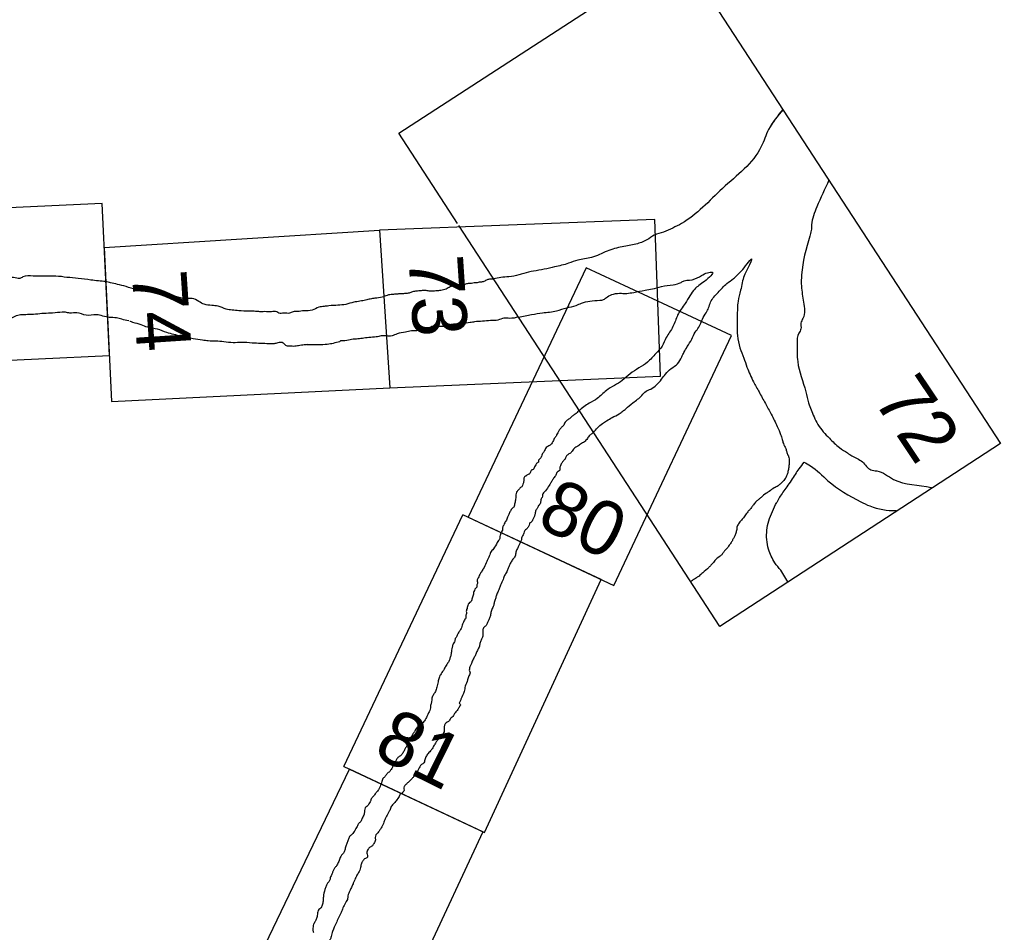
# Model space of a CAD drawing. Extents: x 3953924 to 3974542, y 193747 to 216192.
# Drawn here: x 3962352 to 3963404, y 199042 to 200020 of the extents above; entities that cross this region are included whole.
import ezdxf

# ---------------------------------------------------------------- set-up
doc = ezdxf.new("R2010")
doc.units = 0
doc.layers.add('V-ANNO-NPLT', color=7, linetype='Continuous')

msp = doc.modelspace()

# ---------------------------------------------------------------- linework, layer by layer
at = {"layer": 'V-ANNO-NPLT'}
for p, q in [((3962737.9, 199794.5), (3962749, 199625.4)), ((3963175.8, 199417.6), (3963168.1, 199429.9))]:
    msp.add_line(p, q, dxfattribs=at)
for points in [[(3962758.7, 199898.3), (3963059.7, 200094), (3963403.6, 199565.8), (3963102.7, 199369.7)], [(3962821.6, 199801.6), (3962758.7, 199898.3)], [(3962440.7, 199823.2), (3962163.5, 199810.2)], [(3962448.5, 199660.1), (3962440.7, 199823.2)], [(3962163.5, 199810.2), (3962143.7, 199645.8), (3962448.5, 199660.1)], [(3962737.9, 199794.5), (3962749, 199625.4), (3963039.3, 199637.8), (3963033.3, 199806)], [(3963033.3, 199806), (3962737.9, 199794.5)], [(3962442.9, 199775.9), (3962737.9, 199794.5)], [(3963023.1, 199492.1), (3962822.9, 199799.5)], [(3962442.9, 199775.9), (3962450.8, 199610.7), (3962749, 199625.4)], [(3962959.4, 199754), (3962915.2, 199660.4)], [(3963036.3, 199718.2), (3962959.4, 199754)], [(3962833.1, 199486.7), (3962989.2, 199413.6), (3963115.2, 199681.4), (3963036.3, 199718.2)], [(3962915.2, 199660.4), (3962833.1, 199486.7)], [(3962699.8, 199219.7), (3962827.4, 199489.4)], [(3962975.7, 199420), (3962827.4, 199489.4)], [(3963102.7, 199369.7), (3963023.1, 199492.1)], [(3962699.8, 199219.7), (3962850.6, 199148.7), (3962975.7, 199420)], [(3962722.4, 198877.9), (3962576.5, 198947.1), (3962705.8, 199216.8)], [(3962848.6, 199149.6), (3962705.8, 199216.8)], [(3962848.6, 199149.6), (3962722.4, 198877.9)]]:
    msp.add_lwpolyline(points, dxfattribs=at)
for points in [[(3963170.6, 199923.9), (3963155.1, 199902.3), (3963147.2, 199884), (3963105.7, 199839.2), (3963061.9, 199801.6), (3963042.3, 199792.4)], [(3963170.5, 199923.8), (3963155.1, 199902.3), (3963147.2, 199884), (3963105.7, 199839.2), (3963061.9, 199801.6), (3963042.3, 199792.4)], [(3963219.8, 199848), (3963206.8, 199819.4), (3963201.2, 199800.1), (3963200.8, 199794), (3963199.3, 199788.1), (3963190.5, 199746.7), (3963190.3, 199734.3), (3963192.6, 199717.3), (3963191.9, 199699.8), (3963189.7, 199694.9), (3963189.8, 199688.7), (3963187.4, 199684.1), (3963185.7, 199673.2), (3963186.3, 199653.6), (3963194.9, 199621.3), (3963198, 199609.2), (3963203.8, 199594.5), (3963208, 199586.1), (3963220.3, 199571.4), (3963231, 199561.4), (3963239.8, 199555.6), (3963244.3, 199552.7), (3963255.7, 199546.1), (3963264.8, 199537.5), (3963271.1, 199536.4), (3963289.1, 199527.3), (3963329.4, 199518.5), (3963330.6, 199518.2)], [(3963042.3, 199792.4), (3963032.5, 199789), (3963024.6, 199784.1), (3963012.9, 199779.5), (3962998.2, 199776.7), (3962982, 199772), (3962965.2, 199765.1), (3962950.5, 199762.3), (3962940.7, 199759), (3962925.7, 199755), (3962914.6, 199752.6), (3962903, 199750.5), (3962892.7, 199748.1), (3962887.3, 199746.5), (3962876.7, 199744.5), (3962868.1, 199743.7), (3962860.3, 199742.2)], [(3962967.3, 199577.5), (3962976.9, 199587.2), (3962981.5, 199590.1), (3962987.4, 199593.7), (3962995, 199597.6), (3962998.8, 199600.4), (3963002, 199603), (3963009.6, 199609.4), (3963019.3, 199617.3), (3963023.7, 199621.9), (3963028.7, 199624.1), (3963040.3, 199634.7), (3963044.5, 199640.1), (3963050.6, 199646.1), (3963057.5, 199651.2), (3963062, 199658.6), (3963064.4, 199663.5), (3963067.9, 199669.6), (3963072.7, 199677.7), (3963076.5, 199685), (3963080.2, 199690.5), (3963084.2, 199699.1), (3963088.1, 199706), (3963090.8, 199711.3), (3963092.9, 199717.2), (3963101, 199727.7), (3963110.5, 199737.4), (3963117.3, 199742.5), (3963125.9, 199750.7), (3963132.3, 199758.5), (3963136.8, 199763.6), (3963133.3, 199754.3), (3963128.8, 199745.4), (3963125.1, 199730.1), (3963122.4, 199718.3), (3963121.5, 199702.2), (3963121.7, 199681.4), (3963124.4, 199668.4), (3963128.5, 199657.4), (3963131.9, 199647.6), (3963139, 199631.9), (3963144.9, 199621), (3963151.6, 199608.8), (3963157.9, 199597.2), (3963164.4, 199584), (3963168, 199575.3), (3963169.7, 199570.2)], [(3962886.9, 199701.3), (3962901.1, 199704), (3962912.7, 199705.9), (3962927.8, 199708), (3962938.8, 199711.3), (3962948.9, 199713.8), (3962954.5, 199716.2), (3962963.5, 199718.3), (3962974.1, 199719.4), (3962978.2, 199720.1), (3962982.4, 199723), (3962988.8, 199726), (3962997.4, 199726.8), (3963003, 199726.7), (3963010.5, 199727.8), (3963022.8, 199730), (3963030.5, 199731.5), (3963040.2, 199734), (3963052.9, 199736), (3963061.3, 199738.5), (3963062.2, 199739.1), (3963073.2, 199741.4), (3963083.3, 199745.9), (3963089.6, 199748.9), (3963094.7, 199749.4), (3963086.3, 199739.6), (3963075.9, 199731.3), (3963065.8, 199716), (3963057.6, 199703.4), (3963052.6, 199691.1), (3963045.4, 199679.3), (3963041, 199670.2), (3963034.1, 199662.2), (3963025.3, 199653.1), (3963006.6, 199640.5), (3962998.3, 199633.4), (3962989.9, 199628), (3962981.2, 199622.7), (3962971.5, 199614.1), (3962962.8, 199608.9), (3962951.6, 199601)], [(3962444.5, 199739.3), (3962428.7, 199741), (3962415, 199742.8), (3962402.9, 199743.9), (3962391.1, 199745.2), (3962377, 199745.1), (3962366.6, 199745.2), (3962355.7, 199744.3), (3962352.3, 199742.8), (3962345.8, 199743.6), (3962341.8, 199743.8), (3962332.4, 199742.3), (3962321.3, 199739.2), (3962301.5, 199736)], [(3962597.9, 199707.5), (3962587.2, 199708.1), (3962580, 199708.8), (3962573.6, 199709.9), (3962565, 199712.9), (3962558.2, 199713.8), (3962550.2, 199715), (3962544.2, 199718), (3962537, 199721.2), (3962529.9, 199720.9), (3962519.6, 199723.3), (3962510.4, 199724.8), (3962502.7, 199727.2), (3962498.4, 199726.6), (3962492.5, 199728.6), (3962477.1, 199730.8), (3962466.3, 199734), (3962457, 199736.4), (3962449.7, 199738.1), (3962444.5, 199739.3)], [(3962860.3, 199742.2), (3962857.6, 199742), (3962854.1, 199741.5), (3962851.7, 199740.4), (3962849.9, 199739.3), (3962846.3, 199738.8), (3962843.6, 199738.3), (3962839.5, 199737.9), (3962836.5, 199737.3), (3962831.9, 199737.1), (3962828.8, 199735.9), (3962822.9, 199735.7), (3962819.6, 199734.9), (3962814.9, 199734.1), (3962810.7, 199731.9), (3962805, 199730.1), (3962799.8, 199729.4), (3962794.4, 199729), (3962790, 199729.3), (3962786.2, 199729.9), (3962781.3, 199729.4), (3962776.5, 199729), (3962772.3, 199728.1), (3962768.8, 199726.8), (3962764.8, 199726.4), (3962760.5, 199726.3), (3962756.5, 199725.9), (3962751.9, 199725.6), (3962746.2, 199724.6), (3962740.9, 199722.6), (3962733, 199721.5), (3962728.1, 199720.6), (3962723.1, 199719.5)], [(3962723.1, 199719.5), (3962717, 199718.3), (3962710.4, 199717.2), (3962702, 199714.9), (3962693.5, 199714), (3962683.6, 199713.3), (3962678.5, 199712.7), (3962673, 199711.8), (3962665.9, 199708.7), (3962657.3, 199708), (3962650, 199707.3), (3962645.5, 199707.1), (3962641.4, 199705.4), (3962635.6, 199705.6), (3962630.1, 199705.6), (3962628, 199706.9), (3962622.3, 199707.1), (3962616.7, 199707.1), (3962609.8, 199707.1), (3962604.9, 199707.4), (3962600.5, 199707.7), (3962597.9, 199707.5)], [(3962469.2, 199697.1), (3962461.6, 199698.9), (3962456.2, 199700.4), (3962448.3, 199700.9), (3962434.5, 199703.7), (3962423.4, 199703.3), (3962413.6, 199705.9), (3962406.1, 199705.6), (3962401.3, 199706.4), (3962397.9, 199706.5), (3962387.6, 199705.5), (3962378.5, 199705.2), (3962369.3, 199704.3), (3962360.8, 199703.9), (3962353.3, 199703.6), (3962346.9, 199701.8), (3962341.8, 199700.2), (3962339.2, 199701.9), (3962337.1, 199701.7), (3962334, 199699.7), (3962315.3, 199700.5)], [(3962886.9, 199701.3), (3962877.5, 199699.9), (3962871.4, 199700), (3962864.9, 199698.1), (3962857.1, 199697.5), (3962848.5, 199696.8), (3962839.9, 199696.2), (3962835.2, 199695.4), (3962826.3, 199694.5), (3962819, 199693.8), (3962812.8, 199692.9), (3962807.7, 199691.4), (3962802.6, 199691.3), (3962797.9, 199691.3), (3962794.1, 199691.1), (3962790.3, 199688.3), (3962785.8, 199688), (3962781.6, 199687.1), (3962777.5, 199686.7), (3962772.2, 199686.4), (3962765.8, 199685), (3962756.9, 199683.3), (3962751.4, 199681.1), (3962745.3, 199681.2)], [(3962619.6, 199672.7), (3962601.5, 199673.5), (3962590.2, 199674.2), (3962581.2, 199673.8), (3962571.2, 199674.8), (3962562.5, 199675.5), (3962554.5, 199675.7), (3962548.3, 199676.5), (3962538.1, 199677.9), (3962525.4, 199680.8), (3962510.1, 199684.7), (3962500.1, 199688.3), (3962489.4, 199690.4), (3962482.6, 199692.9), (3962473.7, 199695.6), (3962470.4, 199696.7)], [(3962745.3, 199681.2), (3962739.8, 199681.2), (3962734.5, 199680), (3962726.7, 199679.4), (3962719.6, 199678.4), (3962713.2, 199677.8), (3962706.4, 199677), (3962699, 199675.8), (3962695.4, 199675.3), (3962695.3, 199675.2)], [(3962660.4, 199671.8), (3962658.7, 199671.6), (3962652.7, 199670.8), (3962647.2, 199670), (3962641.2, 199670.1), (3962637.6, 199670.9), (3962634.8, 199673.4), (3962629, 199673.6), (3962624.9, 199672.7), (3962619.6, 199672.7)], [(3962660.4, 199671.8), (3962672.4, 199671.9), (3962682, 199672.3), (3962695.3, 199675.2)], [(3962951.6, 199601), (3962947.8, 199597.1), (3962945.3, 199595.6), (3962943.7, 199594.3), (3962942.3, 199592.9), (3962940.7, 199591.9), (3962939.2, 199590.7), (3962937.7, 199589.4), (3962936.4, 199587.5), (3962935.6, 199585.6), (3962933.7, 199583.8), (3962931.8, 199581.5), (3962930.5, 199579.9), (3962929.1, 199577.3), (3962927.9, 199575.2), (3962927.2, 199573.6), (3962925.4, 199571.1), (3962924.4, 199569.1), (3962921.6, 199564.6), (3962918.6, 199562.7), (3962916.7, 199561.5)], [(3962967.3, 199577.5), (3962964.9, 199575.8), (3962962, 199573.1), (3962960.9, 199571.1), (3962959.2, 199569.2), (3962957.8, 199567.5), (3962955.6, 199566.4), (3962953.5, 199565), (3962951.5, 199563.5), (3962948.4, 199561.8), (3962946.6, 199560.4), (3962945.3, 199558.7), (3962943.9, 199556.7), (3962941.1, 199554.6), (3962938.6, 199552.5), (3962937.1, 199549.5), (3962934.9, 199546.9), (3962932.9, 199543.9), (3962931.9, 199541.8), (3962931.3, 199539), (3962931.2, 199537.2), (3962929.4, 199535.8), (3962928.1, 199534.7), (3962927.5, 199532.8), (3962926.7, 199531.2), (3962925.4, 199529.5), (3962924, 199527.4), (3962922.4, 199524.9), (3962921.4, 199523.1), (3962919.8, 199520.9), (3962915.9, 199514.9), (3962912.7, 199510.6), (3962912.3, 199507.9), (3962911.2, 199506.4), (3962910.8, 199504.1)], [(3962916.7, 199561.5), (3962915.5, 199559.4), (3962914.2, 199556.9), (3962912.5, 199554.3), (3962911.6, 199552)], [(3963169.7, 199570.2), (3963170.9, 199565.8), (3963173.6, 199560.3), (3963174.1, 199558.6), (3963175.1, 199555.1), (3963176.6, 199551.7), (3963177.1, 199547.2), (3963177, 199543.3), (3963176.6, 199538.9), (3963175.6, 199534.5), (3963174.4, 199531), (3963172.2, 199527.3), (3963168.2, 199523), (3963165.4, 199520.5), (3963161.2, 199518.1), (3963155.6, 199514.5), (3963152.7, 199512.5), (3963147, 199508), (3963144.5, 199505.8)], [(3962911.6, 199552), (3962911.3, 199551.1), (3962910.6, 199550.1), (3962909.7, 199549.3), (3962908.6, 199547.8), (3962908.6, 199547.4), (3962908.3, 199546.1), (3962908.3, 199545.6), (3962907.2, 199545.2), (3962905.6, 199542.8), (3962904.3, 199540.9), (3962901.9, 199537.4), (3962900.9, 199537.3), (3962900.1, 199536.3), (3962899.4, 199534.4), (3962898.7, 199533.2), (3962898.1, 199532.8), (3962896.8, 199532.3)], [(3963192.9, 199545.9), (3963187.6, 199538.7), (3963183.5, 199532.7), (3963179.2, 199526.1), (3963174.6, 199519.3), (3963170.5, 199513.5), (3963166.7, 199508.1), (3963163.9, 199502.7)], [(3963192.9, 199545.9), (3963200.1, 199541.8), (3963218.7, 199525.9), (3963253.8, 199503.4), (3963263.8, 199498.8), (3963291.6, 199493.8), (3963291.8, 199493.8)], [(3962896.8, 199532.3), (3962895.3, 199531.2), (3962894.3, 199530.6), (3962892.9, 199529.4), (3962892.6, 199528.1), (3962892.6, 199526.2), (3962892.5, 199524.6), (3962892.3, 199523.5), (3962891.2, 199520.8), (3962890.4, 199519.4), (3962889.3, 199518.5), (3962887.9, 199517.1), (3962886.9, 199516.1), (3962885.9, 199515), (3962885, 199513.8), (3962884.5, 199512.3)], [(3962884.5, 199512.3), (3962884.1, 199509.1), (3962883.9, 199506.2), (3962883.1, 199501.9), (3962882.6, 199499.4), (3962882.4, 199498.3)], [(3962882.4, 199498.3), (3962882.3, 199498.1), (3962881.3, 199497.1), (3962880.4, 199496.3), (3962878.3, 199493.3), (3962876.6, 199489.7), (3962875.3, 199486.9), (3962874.6, 199484.5), (3962873.5, 199482.7), (3962871.1, 199478.4), (3962869.9, 199475.4), (3962869.9, 199472.7), (3962868.6, 199470.7), (3962867.8, 199468.5), (3962867.3, 199467.4), (3962867.1, 199464.7), (3962865.7, 199461.9), (3962864.2, 199459.6), (3962860.2, 199452.9), (3962857.1, 199449), (3962855.2, 199443.9), (3962853.7, 199441), (3962852.4, 199437.7), (3962849.2, 199431.5), (3962847.2, 199428), (3962845.6, 199425.3), (3962843.2, 199420.5), (3962842.7, 199419), (3962843.1, 199417.1), (3962842.3, 199414.3)], [(3962910.8, 199504.1), (3962909.6, 199500.4), (3962908.6, 199499.2), (3962907.8, 199497.5), (3962906.2, 199495), (3962905.4, 199493.3), (3962904.5, 199489.5), (3962902.1, 199483.6), (3962901.1, 199481.8), (3962899.2, 199480.6), (3962898.3, 199478.2), (3962896.8, 199475.5), (3962895.5, 199473.8), (3962893.7, 199472.4), (3962892.8, 199469.5), (3962891.9, 199467.7), (3962890.8, 199466.1), (3962890.1, 199462.5), (3962888.9, 199459.7), (3962888.1, 199457.7), (3962886.6, 199454.9), (3962885.8, 199453.3), (3962884.2, 199449.3), (3962883.3, 199444.9), (3962880.9, 199441.7), (3962878.7, 199438.2), (3962876.5, 199433.6), (3962875.3, 199430.4), (3962873.2, 199426.2), (3962871.1, 199422.5), (3962870.5, 199420.1)], [(3963144.5, 199505.8), (3963141.9, 199503.6), (3963138.8, 199500.1), (3963136.7, 199497.2), (3963135.1, 199495), (3963132.8, 199492.6), (3963129.7, 199488.1), (3963126.8, 199484.5), (3963123.5, 199480.7), (3963121.5, 199477), (3963120.7, 199472.6), (3963119.6, 199468.6), (3963118.2, 199465.2), (3963116.5, 199462.5), (3963116, 199461.2)], [(3963168.1, 199429.9), (3963161.8, 199437.9), (3963155.1, 199452.4), (3963153.1, 199462.8), (3963155.3, 199482.8), (3963163.9, 199502.7)], [(3963116, 199461.2), (3963113.8, 199457.9), (3963110.3, 199453.3), (3963108, 199450.7), (3963106.2, 199448.4), (3963104.3, 199445.9), (3963099.5, 199442.5), (3963095.9, 199438.2), (3963093.2, 199435.3), (3963091, 199432.8), (3963084.5, 199427.2), (3963080.5, 199423.7), (3963077.7, 199421.9)], [(3962870.5, 199420.1), (3962867.6, 199413.8), (3962866.2, 199410), (3962865.3, 199407.6), (3962863.3, 199403.2), (3962862.4, 199399.4), (3962861, 199395.5), (3962860.7, 199393.6), (3962858.9, 199388.9), (3962857.5, 199384.5), (3962856.6, 199380.4), (3962855.2, 199376.9), (3962853.6, 199373.8), (3962852.3, 199370.6), (3962851, 199369.5), (3962848.8, 199366.3), (3962848.8, 199363.4), (3962848.6, 199359.1), (3962847.3, 199355.9), (3962845.9, 199352.4), (3962845.1, 199348.6), (3962842.9, 199344), (3962841.1, 199339.9), (3962839.6, 199336.6), (3962837.4, 199332.6), (3962836.2, 199329.2), (3962834.7, 199326.5), (3962834.3, 199323.8)], [(3962842.3, 199414.3), (3962842.2, 199411.8), (3962841.2, 199410.6), (3962839.7, 199408.2), (3962838.9, 199406.1)], [(3963077.7, 199421.9), (3963075.5, 199420.4), (3963074, 199419.5), (3963071.5, 199417.7)], [(3962838.9, 199406.1), (3962838.6, 199404.4), (3962838, 199402.3), (3962837.4, 199400), (3962836.9, 199397.7)], [(3962836.9, 199397.7), (3962836.6, 199397.1), (3962835.4, 199395.8), (3962834.6, 199395.2), (3962833, 199393.4), (3962832.3, 199390.9), (3962831.8, 199388.8), (3962831.1, 199386.6), (3962831.1, 199384.8), (3962830.9, 199382.6), (3962830.4, 199380.6), (3962830.4, 199378.7), (3962829.5, 199377.3), (3962828.5, 199375.2), (3962827.7, 199373.5), (3962826.7, 199370.9), (3962826, 199368.3), (3962825, 199366.5), (3962824.1, 199365.1), (3962821.9, 199361.6), (3962820.8, 199359.1), (3962819.1, 199356.6)], [(3962819.1, 199356.6), (3962818.3, 199353.2), (3962817, 199350.9), (3962816, 199347.3), (3962815.3, 199344.2), (3962815, 199342.6)], [(3962815, 199342.6), (3962814.7, 199340), (3962813.8, 199336.4), (3962812.7, 199333.1), (3962811.8, 199331.2), (3962810.9, 199330.3)], [(3962810.9, 199330.4), (3962810.6, 199329.7), (3962808.3, 199325.9), (3962807.2, 199323.7), (3962804, 199319), (3962801.9, 199314.7), (3962800.8, 199310.2), (3962799.5, 199304.7), (3962797.9, 199299.8), (3962795.9, 199296.7), (3962794.2, 199292.7), (3962793.7, 199288.3), (3962792.8, 199285), (3962792, 199279.7), (3962790.2, 199276.3), (3962789.5, 199274.6), (3962788.7, 199273)], [(3962834.3, 199323.8), (3962834.4, 199321.9), (3962835, 199321), (3962833.8, 199316.7), (3962832.4, 199312.3), (3962830, 199305.7), (3962828.6, 199299.8), (3962825.3, 199291.8), (3962824.1, 199289), (3962823.5, 199287.5), (3962824.1, 199286.6), (3962824.6, 199286.3), (3962823.8, 199283.7), (3962821.9, 199280.5), (3962819, 199277.2), (3962817.3, 199274.1), (3962814.2, 199271), (3962811.8, 199267.7), (3962809.6, 199266.5), (3962807.8, 199263.7), (3962807.3, 199260.7), (3962807.4, 199258.1), (3962806.7, 199255.5), (3962804.2, 199251.9), (3962801.4, 199248.7), (3962798.7, 199245.8), (3962797.3, 199243.4), (3962796.5, 199242.3)], [(3962788.7, 199273), (3962786.8, 199269.4), (3962784.2, 199266), (3962782.3, 199263.9), (3962778.4, 199261.5), (3962775.8, 199257.5), (3962773.9, 199254.5), (3962772.7, 199252.5), (3962770.6, 199249.2), (3962768.4, 199243.6), (3962766.9, 199240.9), (3962765.1, 199238), (3962763.5, 199234.9), (3962761.1, 199231.6), (3962758.4, 199229.7), (3962756.3, 199226.9), (3962754.8, 199224.1), (3962753, 199221.2), (3962751.9, 199218.7), (3962750.4, 199216.3), (3962748.3, 199213.5), (3962746.6, 199212.5), (3962746.3, 199212)], [(3962796.5, 199242.3), (3962794.5, 199238.6), (3962791.8, 199235.4), (3962788.9, 199231.8), (3962786.9, 199227.9), (3962785.5, 199223.4), (3962783.1, 199221.6), (3962779.9, 199216.7), (3962777.9, 199213.3), (3962775.1, 199209.2), (3962772.9, 199206.6), (3962768.6, 199202.5), (3962766.2, 199200.1), (3962764.3, 199198), (3962764.1, 199195.5), (3962764.1, 199193.1), (3962762.8, 199191.7), (3962762.4, 199191.1)], [(3962746.3, 199212), (3962744.2, 199209.2), (3962741.7, 199206.5), (3962740.2, 199202.2), (3962738, 199196.7), (3962736.5, 199194), (3962733.9, 199190.9), (3962731.5, 199187.6), (3962729.2, 199184.7), (3962727.9, 199181.5), (3962726.7, 199179.6), (3962724.4, 199176.6), (3962722.6, 199175.2), (3962722, 199172.4), (3962721.5, 199168.5), (3962719.5, 199164), (3962718, 199160.7), (3962715.8, 199158.5), (3962714, 199155.2), (3962712.5, 199152.9)], [(3962762.4, 199191.1), (3962759.7, 199189.2), (3962758.9, 199187.5), (3962755.9, 199182.9), (3962752.8, 199179.2), (3962750.1, 199175.5), (3962748.5, 199171.5), (3962746.9, 199168.7), (3962744.2, 199163.5), (3962742.2, 199158.6), (3962740.9, 199155.5), (3962738.9, 199152.4), (3962737, 199149.4), (3962733.6, 199144.9), (3962733.5, 199142.2), (3962733.7, 199140.8), (3962731.9, 199137.1), (3962730.4, 199134.6), (3962727.9, 199133), (3962725.7, 199130.8), (3962724.4, 199126.7), (3962725.1, 199124.2), (3962725.3, 199122.8), (3962722.9, 199121), (3962721.3, 199119.7), (3962720.1, 199118.4), (3962719.3, 199117.3)], [(3962712.5, 199152.9), (3962711.9, 199151.5), (3962710.9, 199150), (3962709.5, 199147.8), (3962708.8, 199147.1), (3962707.5, 199146.1)], [(3962707.5, 199146.1), (3962706.5, 199145.1), (3962705.6, 199143.6), (3962704.2, 199139.8), (3962702.6, 199136.1), (3962701.3, 199132), (3962700.2, 199128.1), (3962696.5, 199123.1), (3962694.6, 199118.6), (3962693, 199114.9), (3962691.5, 199112.5), (3962690.3, 199111.2)], [(3962690.3, 199111.2), (3962688.8, 199108.4), (3962687.5, 199105.7), (3962686.2, 199102.3), (3962685.1, 199100.3), (3962685, 199098.8)], [(3962719.4, 199117.4), (3962718.1, 199113.7), (3962717.7, 199111.1), (3962715.6, 199105.9), (3962713.2, 199102), (3962710.9, 199096.7), (3962709.6, 199093.6), (3962707.8, 199089.8), (3962706.2, 199086.1), (3962705, 199083.8), (3962704.1, 199080.9), (3962703.6, 199077), (3962702.3, 199074.7), (3962701.7, 199073.4)], [(3962685, 199098.8), (3962684.5, 199097.3), (3962682.4, 199094.5), (3962680.8, 199091.4), (3962679.5, 199087.7), (3962677.8, 199080), (3962677.6, 199075.1), (3962676.4, 199070.8), (3962674.9, 199067.5), (3962673.1, 199066.1), (3962671.4, 199061.2), (3962670.5, 199056.5), (3962669.1, 199053.5), (3962668.4, 199052.3)], [(3962701.7, 199073.4), (3962698.8, 199067.9), (3962696.9, 199062.9), (3962694.1, 199057.3), (3962691.5, 199051.5), (3962687.7, 199042.8), (3962686.2, 199037.2), (3962685.1, 199034.1), (3962681.6, 199029.2), (3962681.4, 199025.8), (3962681.6, 199020.7), (3962681.7, 199019.5), (3962682.3, 199017.2)], [(3962668.4, 199052.3), (3962667.4, 199050.4), (3962666.8, 199047.6), (3962666.6, 199044.8), (3962666.8, 199042.9), (3962667.2, 199041.7)]]:
    msp.add_spline(points, degree=3, dxfattribs=at)

# ---------------------------------------------------------------- texts
for s, rotation, p in [('73', 273.7738, (3962768.9, 199765.8)), ('74', 273.7738, (3962472.5, 199749.7)), ('72', 303.7738, (3963266.2, 199613.1)), ('80', 333.7738, (3962904.7, 199478.3)), ('81', 333.7738, (3962729.5, 199231.8))]:
    msp.add_text(s, height=58.5, rotation=rotation, dxfattribs=at).set_placement(p)

doc.saveas('drawing.dxf')
